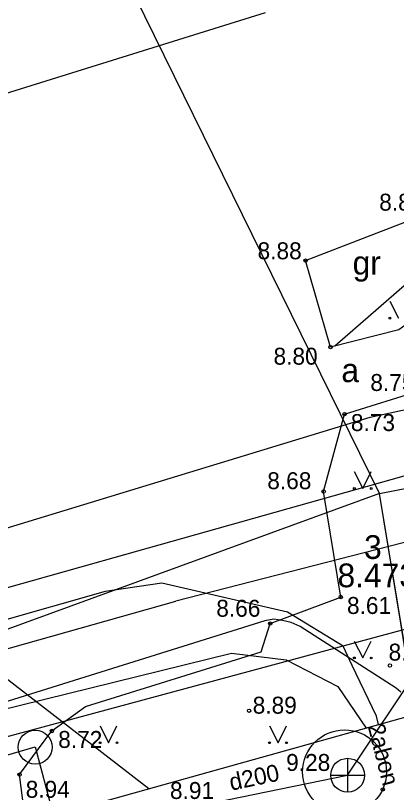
# Model space of a CAD drawing. Extents: x 496078 to 496285, y 304225 to 304369.
# Drawn here: x 496157.26 to 496168.49, y 304288.53 to 304311.46 of the extents above; entities that cross this region are included whole.
import ezdxf

# ---------------------------------------------------------------- set-up
doc = ezdxf.new("R2010")
doc.units = 0
for name, color, linetype in [('APGR_AIZS_####_####_#', 7, 'Continuous'), ('APGR_ELEM_####_####_#', 7, 'Continuous'), ('APGR_SARK_####_####_#', 7, 'Continuous'), ('APGS_VADP_ZSPR_####_#', 7, 'Continuous'), ('CELI_CMAL_####_####_#', 7, 'Continuous'), ('CELI_CSEG_####_TKST_#', 7, 'Continuous'), ('ELEK_VADP_ZSPR_####_#', 7, 'Continuous'), ('ELEK_VADP_ZSPR_TKST_#', 7, 'Continuous'), ('ELEK_VADV_ZSPR_####_#', 7, 'Continuous'), ('GEOD_ELEM_####_TKST_#', 7, 'Continuous'), ('Level 13', 7, 'Continuous'), ('Level 21', 7, 'Continuous'), ('Level 24', 7, 'Continuous'), ('RAMI_UZMR_####_####_#', 7, 'Continuous'), ('RELJ_AATZ_####_TKST_#', 7, 'Continuous'), ('RELJ_ELEM_####_####_#', 7, 'Continuous'), ('SAKT_VADP_KABE_####_#', 7, 'Continuous'), ('SAKT_VADP_NEDR_####_#', 7, 'Continuous'), ('SKAN_DETP_SPDK_####_#', 7, 'Continuous'), ('SKAN_ELEM_####_####_#', 7, 'Continuous'), ('SKAN_ELEM_PAST_TKST_#', 7, 'Continuous'), ('SKAN_ELEM_SPDK_TKST_#', 7, 'Continuous'), ('SKAN_VADP_PAST_####_#', 7, 'Continuous'), ('SKAN_VADP_PAST_TKST_#', 7, 'Continuous'), ('TERT_ELEM_####_####_#', 7, 'Continuous'), ('UDTK_VADP_UDEN_####_#', 7, 'Continuous')]:
    doc.layers.add(name, color=color, linetype=linetype)

msp = doc.modelspace()

# ---------------------------------------------------------------- linework, layer by layer
at = {"layer": 'APGR_AIZS_####_####_#'}
msp.add_lwpolyline([(496171.482, 304276.481), (496169.303, 304289.245), (496168.626, 304293.523), (496167.995, 304297.351), (496154.713, 304324.372)], dxfattribs=at)
at = {"layer": 'APGR_ELEM_####_####_#'}
msp.add_circle((496157.84, 304289.87), 0.5, dxfattribs=at)
at = {"layer": 'APGR_SARK_####_####_#'}
for p, q in [((496149.627, 304287.537), (496157.839, 304289.874)), ((496157.839, 304289.874), (496160.071, 304281.452))]:
    msp.add_line(p, q, dxfattribs=at)
at = {"layer": 'APGS_VADP_ZSPR_####_#'}
for p, q in [((496167.718, 304299.606), (496170.565, 304300.222)), ((496153.427, 304295.248), (496167.718, 304299.606))]:
    msp.add_line(p, q, dxfattribs=at)
at = {"layer": 'CELI_CMAL_####_####_#'}
for points in [[(496169.864, 304303.13), (496168.559, 304302.187), (496166.548, 304301.675), (496165.812, 304304.226), (496169.3, 304305.578), (496176.443, 304307.431), (496192.141, 304311.641)], [(496166.677, 304301.708), (496169.783, 304304.413), (496176.513, 304306.904), (496192.208, 304311.128)], [(496158.075, 304283.625), (496157.379, 304289.059), (496158.33, 304290.346), (496159.317, 304291.067), (496164.506, 304292.685), (496164.77, 304293.516), (496166.848, 304294.299), (496166.345, 304297.413), (496166.963, 304299.697), (496169.291, 304300.424), (496170.044, 304300.38), (496170.481, 304300.514)]]:
    msp.add_lwpolyline(points, dxfattribs=at)
at = {"layer": 'ELEK_VADP_ZSPR_####_#'}
for p, q in [((496161.573, 304294.71), (496159.906, 304294.464)), ((496165.28, 304293.85), (496161.573, 304294.71)), ((496159.906, 304294.464), (496153.785, 304292.72)), ((496166.92, 304292.844), (496165.28, 304293.85)), ((496164.614, 304293.595), (496154.662, 304290.482)), ((496164.873, 304293.643), (496164.614, 304293.595)), ((496165.132, 304293.611), (496164.873, 304293.643)), ((496165.391, 304293.544), (496165.132, 304293.611)), ((496165.65, 304293.428), (496165.391, 304293.544)), ((496168.487, 304291.61), (496165.65, 304293.428)), ((496154.843, 304290.483), (496163.624, 304292.643)), ((496163.624, 304292.643), (496165.242, 304292.447)), ((496167.188, 304292.281), (496166.92, 304292.844)), ((496165.242, 304292.447), (496166.763, 304291.661)), ((496167.901, 304290.781), (496167.188, 304292.281)), ((496166.763, 304291.661), (496167.595, 304290.433)), ((496168.618, 304291.487), (496168.487, 304291.61)), ((496167.961, 304290.535), (496167.901, 304290.781))]:
    msp.add_line(p, q, dxfattribs=at)
at = {"layer": 'ELEK_VADV_ZSPR_####_#'}
msp.add_line((496129.299, 304313.334), (496161.188, 304288.645), dxfattribs=at)
at = {"layer": 'Level 13'}
msp.add_lwpolyline([(496167.995, 304297.351), (496176.843, 304299.089)], dxfattribs=at)
at = {"layer": 'Level 21'}
msp.add_lwpolyline([(496164.622, 304311.533), (496119.806, 304297.572)], dxfattribs=at)
at = {"layer": 'Level 24'}
for points in [[(496167.995, 304297.351), (496143.254, 304288.326)], [(496170.693, 304281.022), (496167.995, 304297.351)]]:
    msp.add_lwpolyline(points, dxfattribs=at)
at = {"layer": 'RAMI_UZMR_####_####_#'}
msp.add_line((496139.922, 304282.712), (496195.979, 304298.352), dxfattribs=at)
at = {"layer": 'RELJ_ELEM_####_####_#'}
for centre in [(496165.812, 304304.226), (496166.548, 304301.675), (496166.963, 304299.697), (496166.345, 304297.413), (496166.848, 304294.299), (496164.77, 304293.516), (496168.301, 304292.278), (496164.145, 304290.944), (496158.33, 304290.346), (496157.379, 304289.059), (496168.087, 304288.622)]:
    msp.add_circle(centre, 0.05, dxfattribs=at)
at = {"layer": 'SAKT_VADP_KABE_####_#'}
msp.add_lwpolyline([(496167.053, 304289.039), (496173.605, 304298.868), (496174.688, 304299.362), (496178.745, 304300.248), (496183.885, 304301.628), (496183.489, 304302.815), (496183.729, 304303.26), (496186.359, 304304.549), (496192.281, 304306.153)], dxfattribs=at)
at = {"layer": 'SAKT_VADP_NEDR_####_#'}
for p, q in [((496156.74, 304294.499), (496174.76, 304299.582)), ((496172.796, 304296.952), (496161.985, 304294.172)), ((496153.87, 304291.887), (496161.985, 304294.172))]:
    msp.add_line(p, q, dxfattribs=at)
at = {"layer": 'SKAN_DETP_SPDK_####_#'}
msp.add_circle((496166.963, 304289.14), 1.237, dxfattribs=at)
at = {"layer": 'SKAN_ELEM_####_####_#'}
for p, q in [((496167.053, 304289.539), (496167.053, 304288.539)), ((496166.553, 304289.039), (496167.553, 304289.039))]:
    msp.add_line(p, q, dxfattribs=at)
msp.add_circle((496167.053, 304289.039), 0.5, dxfattribs=at)
at = {"layer": 'SKAN_VADP_PAST_####_#'}
msp.add_line((496161.56, 304287.922), (496167.053, 304289.039), dxfattribs=at)
at = {"layer": 'TERT_ELEM_####_####_#'}
for p, q in [((496168.302, 304303.031), (496168.552, 304302.531)), ((496167.25, 304298), (496167.5, 304297.5)), ((496167.5, 304297.5), (496167.75, 304298)), ((496167.25, 304293), (496167.5, 304292.5)), ((496167.5, 304292.5), (496167.75, 304293)), ((496159.75, 304290.5), (496160, 304290)), ((496160, 304290), (496160.25, 304290.5)), ((496164.75, 304290.5), (496165, 304290)), ((496165, 304290), (496165.25, 304290.5))]:
    msp.add_line(p, q, dxfattribs=at)
for centre, radius in [((496168.301, 304302.53), 0.028), ((496167.25, 304297.5), 0.028), ((496167.75, 304297.5), 0.0263), ((496167.25, 304292.5), 0.028), ((496167.75, 304292.5), 0.0263), ((496159.75, 304290), 0.028), ((496160.25, 304290), 0.0263), ((496164.75, 304290), 0.028), ((496165.25, 304290), 0.0263)]:
    msp.add_circle(centre, radius, dxfattribs=at)
at = {"layer": 'UDTK_VADP_UDEN_####_#'}
msp.add_line((496154.678, 304289.554), (496173.247, 304294.572), dxfattribs=at)

# ---------------------------------------------------------------- texts
at = {"layer": 'CELI_CSEG_####_TKST_#'}
for s, p in [('gr', (496167.2, 304303.811)), ('a', (496166.868, 304300.64))]:
    msp.add_text(s, height=0.7, dxfattribs=at).set_placement(p)
at = {"layer": 'ELEK_VADP_ZSPR_TKST_#'}
msp.add_text('2abon', height=0.5, rotation=284.2117, dxfattribs=at).set_placement((496167.641, 304290.496))
at = {"layer": 'GEOD_ELEM_####_TKST_#'}
for s, p in [(' 3', (496167.278, 304295.423)), (' 8.473', (496166.494, 304294.588))]:
    msp.add_text(s, height=0.7, dxfattribs=at).set_placement(p)
at = {"layer": 'RELJ_AATZ_####_TKST_#'}
for s, p in [(' 8.87', (496167.798, 304305.7)), (' 8.88', (496164.211, 304304.265)), (' 8.80', (496164.681, 304301.155)), (' 8.75', (496167.536, 304300.379)), (' 8.73', (496166.963, 304299.197)), (' 8.68', (496164.497, 304297.481)), (' 8.66', (496162.993, 304293.717)), (' 8.61', (496166.848, 304293.799)), (' 8.89', (496168.075, 304292.422)), (' 8.89', (496164.066, 304290.857)), (' 8.72', (496158.33, 304289.846))]:
    msp.add_text(s, height=0.5, dxfattribs=at).set_placement(p)
at = {"layer": 'SKAN_ELEM_PAST_TKST_#'}
for s, p in [(' 8.94', (496157.372, 304288.375)), (' 8.91', (496161.627, 304288.34))]:
    msp.add_text(s, height=0.5, dxfattribs=at).set_placement(p)
at = {"layer": 'SKAN_ELEM_SPDK_TKST_#'}
msp.add_text('9.28', height=0.5, dxfattribs=at).set_placement((496165.239, 304289.167))
at = {"layer": 'SKAN_VADP_PAST_TKST_#'}
msp.add_text('d200', height=0.5, rotation=11.8929, dxfattribs=at).set_placement((496163.618, 304288.582))

doc.saveas('drawing.dxf')
